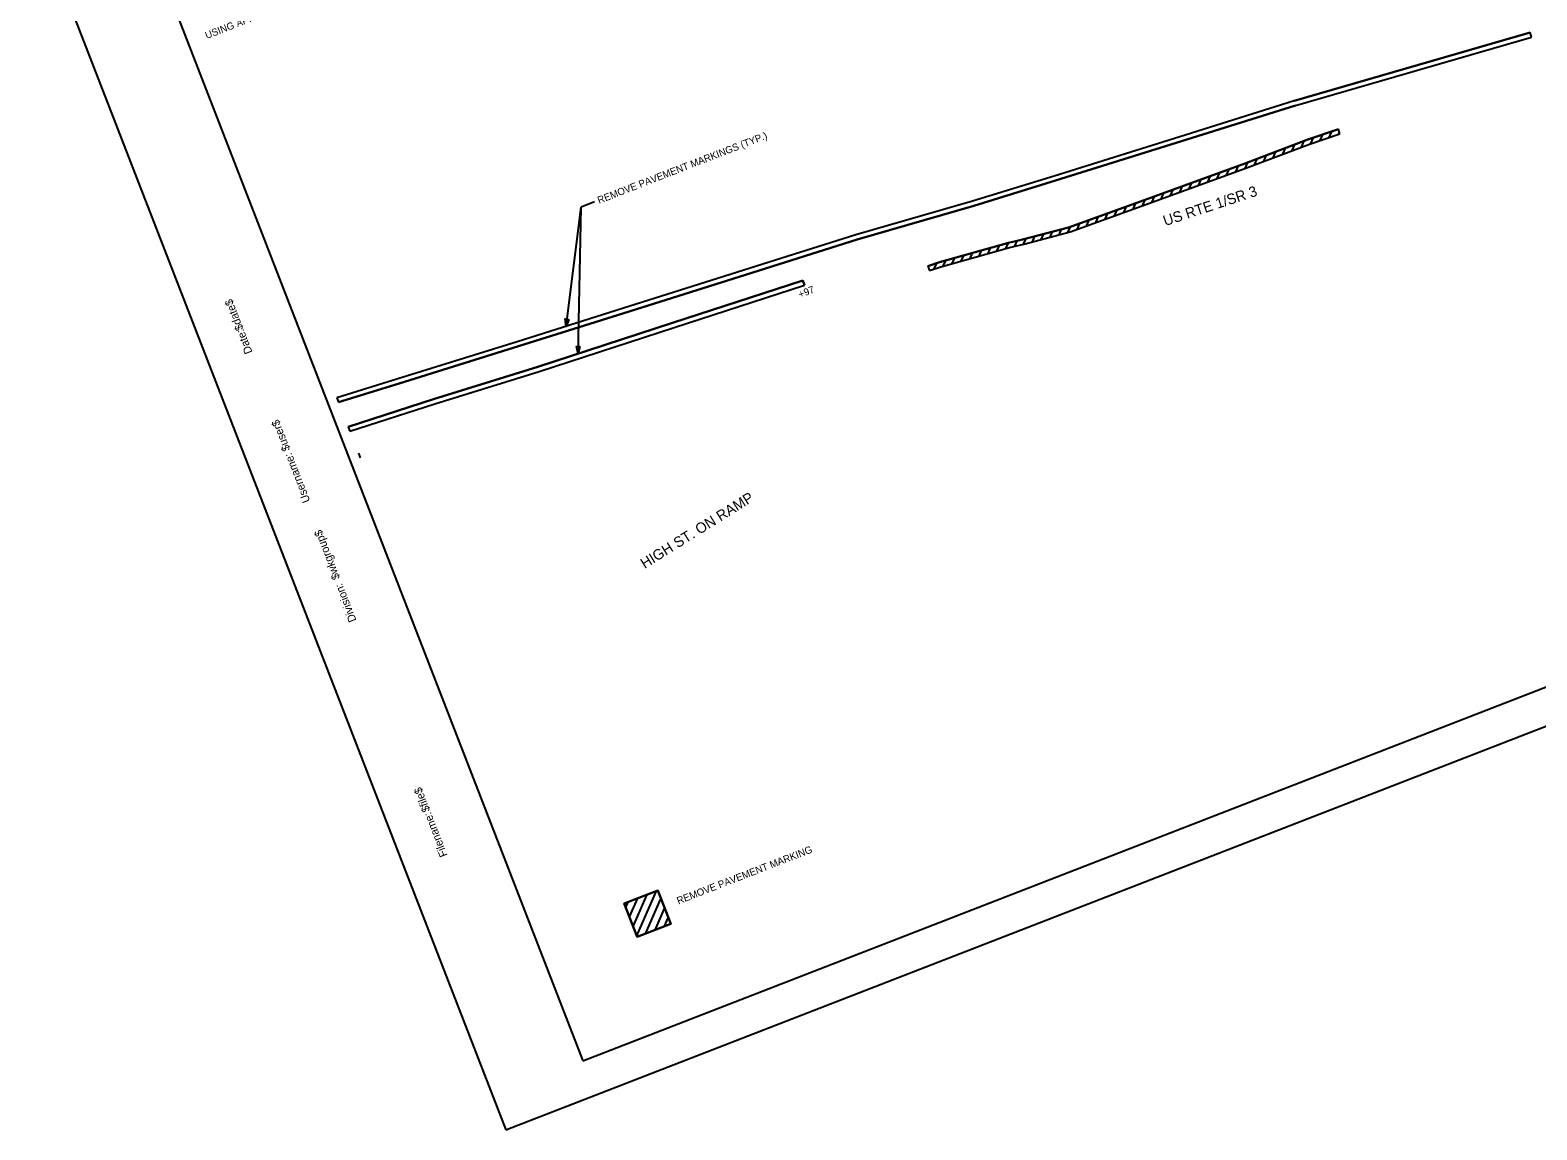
# Model space of a CAD drawing. Extents: x 1669098 to 1670090, y 339554 to 340375.
# Drawn here: x 1669098 to 1669728, y 339554 to 340014 of the extents above; entities that cross this region are included whole.
import ezdxf

# ---------------------------------------------------------------- set-up
doc = ezdxf.new("R2010")
doc.units = 0
for name, color, linetype in [('ANNOTATION', 7, 'Continuous'), ('BORDER', 7, 'Continuous'), ('PATTERNING', 7, 'Continuous'), ('PLOT BOUNDARY', 7, 'Continuous'), ('SHADING', 7, 'Continuous')]:
    doc.layers.add(name, color=color, linetype=linetype)

msp = doc.modelspace()

# ---------------------------------------------------------------- linework, layer by layer
at = {"layer": 'ANNOTATION'}
for p in [(1669334.25, 339942.45), (1669334.25, 339942.45), (1669334.25, 339942.45), (1669322.42, 339890.41), (1669327.39, 339878.97)]:
    msp.add_line(p, (1669328.66, 339940.28), dxfattribs=at)
for points in [[(1669323.54, 339893.3), (1669322.42, 339890.41), (1669322.05, 339893.48)], [(1669328.2, 339881.95), (1669327.39, 339878.97), (1669326.7, 339881.98)]]:
    msp.add_lwpolyline(points, close=True, dxfattribs=at)
at = {"layer": 'BORDER'}
for p, q in [((1669139.46, 340072.86), (1669329.32, 339583.39)), ((1669329.32, 339583.39), (1670075.18, 339872.71))]:
    msp.add_line(p, q, dxfattribs=at)
at = {"layer": 'PATTERNING'}
for p, q in [((1669626.94, 339984.72), (1669725.55, 340013.18)), ((1669725.55, 340013.18), (1669626.94, 339984.72)), ((1669627.49, 339982.8), (1669726.11, 340011.26)), ((1669627.49, 339982.8), (1669726.11, 340011.26)), ((1669726.11, 340011.26), (1669725.55, 340013.18)), ((1669726.11, 340011.26), (1669725.55, 340013.18)), ((1669629.98, 339965.36), (1669631.11, 339967.93)), ((1669632.67, 339968.51), (1669645.39, 339972.8)), ((1669633.3, 339966.62), (1669646.03, 339970.9)), ((1669633.9, 339966.82), (1669634.99, 339969.3)), ((1669637.75, 339968.12), (1669638.84, 339970.59)), ((1669641.6, 339969.41), (1669642.69, 339971.89)), ((1669646.03, 339970.9), (1669645.39, 339972.8)), ((1669645.45, 339970.71), (1669645.82, 339971.54)), ((1669610.3, 339957.93), (1669611.44, 339960.5)), ((1669614.24, 339959.42), (1669615.37, 339961.98)), ((1669618.17, 339960.9), (1669619.3, 339963.47)), ((1669622.11, 339962.39), (1669623.24, 339964.95)), ((1669626.04, 339963.88), (1669627.17, 339966.44)), ((1669594.65, 339952.17), (1669595.77, 339954.71)), ((1669598.56, 339953.6), (1669599.68, 339956.13)), ((1669602.46, 339955.02), (1669603.58, 339957.55)), ((1669606.37, 339956.44), (1669607.5, 339959.01)), ((1669579.03, 339946.48), (1669580.14, 339949.02)), ((1669582.93, 339947.91), (1669584.05, 339950.44)), ((1669586.84, 339949.33), (1669587.96, 339951.86)), ((1669590.74, 339950.75), (1669591.86, 339953.29)), ((1669559.5, 339939.38), (1669560.61, 339941.91)), ((1669563.4, 339940.79), (1669564.52, 339943.33)), ((1669567.31, 339942.22), (1669568.43, 339944.75)), ((1669571.21, 339943.64), (1669572.33, 339946.17)), ((1669575.12, 339945.06), (1669576.24, 339947.6)), ((1669543.9, 339933.76), (1669545.02, 339936.29)), ((1669547.8, 339935.16), (1669548.92, 339937.69)), ((1669551.7, 339936.57), (1669552.82, 339939.1)), ((1669555.6, 339937.97), (1669556.72, 339940.5)), ((1669521.13, 339926.73), (1669522.17, 339929.07)), ((1669524.84, 339927.71), (1669525.87, 339930.04)), ((1669528.55, 339928.68), (1669529.58, 339931.01)), ((1669532.26, 339929.65), (1669533.32, 339932.07)), ((1669536.11, 339930.95), (1669537.22, 339933.48)), ((1669540.01, 339932.35), (1669541.12, 339934.88)), ((1669498.86, 339920.84), (1669499.91, 339923.21)), ((1669502.6, 339921.88), (1669503.65, 339924.25)), ((1669506.34, 339922.93), (1669507.39, 339925.3)), ((1669510.04, 339923.89), (1669511.06, 339926.2)), ((1669513.72, 339924.79), (1669514.75, 339927.13)), ((1669517.43, 339925.76), (1669518.46, 339928.1)), ((1669476.35, 339914.4), (1669477.44, 339916.86)), ((1669480.16, 339915.6), (1669481.2, 339917.97)), ((1669483.9, 339916.65), (1669484.94, 339919.02)), ((1669487.64, 339917.7), (1669488.68, 339920.07)), ((1669491.38, 339918.74), (1669492.42, 339921.11)), ((1669495.12, 339919.79), (1669496.17, 339922.16)), ((1669473.7, 339915.62), (1669474.32, 339913.72)), ((1669421.43, 339909.52), (1669422.04, 339907.61)), ((1669422.04, 339907.61), (1669421.43, 339909.52)), ((1669227.23, 339858.7), (1669252.62, 339866.56)), ((1669226.51, 339860.57), (1669227.23, 339858.7)), ((1669226.51, 339860.57), (1669227.23, 339858.7)), ((1669231.23, 339848.39), (1669231.96, 339846.53)), ((1669231.23, 339848.39), (1669231.96, 339846.53)), ((1669235.52, 339837.35), (1669236.24, 339835.48)), ((1669350.44, 339639.56), (1669356.3, 339652.85)), ((1669351.98, 339635.6), (1669360.26, 339654.38)), ((1669347.37, 339647.47), (1669348.39, 339649.78)), ((1669348.91, 339643.51), (1669352.35, 339651.32)), ((1669355.65, 339636.51), (1669362.07, 339651.06)), ((1669359.61, 339638.04), (1669363.6, 339647.1)), ((1669363.57, 339639.58), (1669365.14, 339643.15))]:
    msp.add_line(p, q, dxfattribs=at)
for points in [[(1669626.94, 339984.72), (1669581.38, 339970.39), (1669526.5, 339953.23), (1669492.4, 339942.67), (1669443.62, 339928.65), (1669396.79, 339913.89), (1669343.28, 339897.01), (1669301.86, 339883.98), (1669252.02, 339868.47), (1669226.51, 339860.57)], [(1669626.91, 339984.71), (1669581.38, 339970.39), (1669526.5, 339953.23), (1669492.4, 339942.67), (1669443.62, 339928.65), (1669396.79, 339913.89), (1669343.28, 339897.01), (1669301.86, 339883.98), (1669252.02, 339868.47), (1669226.51, 339860.57)], [(1669627.51, 339982.8), (1669581.98, 339968.48), (1669527.09, 339951.32), (1669492.97, 339940.75), (1669444.19, 339926.74), (1669397.39, 339911.99), (1669343.88, 339895.1), (1669302.45, 339882.07), (1669252.62, 339866.56), (1669227.23, 339858.7)], [(1669252.62, 339866.56), (1669302.45, 339882.07), (1669343.88, 339895.1), (1669397.39, 339911.99), (1669444.19, 339926.74), (1669492.97, 339940.75), (1669527.09, 339951.32), (1669581.98, 339968.48), (1669627.49, 339982.8)], [(1669473.7, 339915.62), (1669478.5, 339917.22), (1669507.37, 339925.3), (1669513.28, 339926.74), (1669532.56, 339931.79), (1669560.71, 339941.94), (1669605.52, 339958.26), (1669632.63, 339968.5)], [(1669474.32, 339913.72), (1669479.08, 339915.3), (1669507.88, 339923.36), (1669513.77, 339924.81), (1669533.15, 339929.88), (1669561.39, 339940.06), (1669606.21, 339956.38), (1669633.34, 339966.63)], [(1669231.23, 339848.39), (1669266.9, 339859.9), (1669310.56, 339873.49), (1669366.96, 339891.87), (1669421.43, 339909.52)], [(1669421.43, 339909.52), (1669366.96, 339891.87), (1669310.56, 339873.49), (1669266.9, 339859.9), (1669231.23, 339848.39)], [(1669231.96, 339846.53), (1669267.5, 339857.99), (1669311.17, 339871.58), (1669367.57, 339889.96), (1669422.04, 339907.61)], [(1669231.96, 339846.53), (1669267.5, 339857.99), (1669311.17, 339871.58), (1669367.57, 339889.96), (1669422.04, 339907.61)]]:
    msp.add_lwpolyline(points, dxfattribs=at)
msp.add_lwpolyline([(1669346.73, 339649.14), (1669360.71, 339654.56), (1669366.14, 339640.58), (1669352.15, 339635.15)], close=True, dxfattribs=at)
at = {"layer": 'PLOT BOUNDARY'}
msp.add_lwpolyline([(1669297.13, 339554.5), (1670089.6, 339861.9), (1669890.69, 340374.67), (1669098.22, 340067.27)], close=True, dxfattribs=at)
at = {"layer": 'SHADING'}
for p, q in [((1669725.55, 340013.18), (1669626.94, 339984.72)), ((1669627.49, 339982.8), (1669726.11, 340011.26)), ((1669726.11, 340011.26), (1669725.55, 340013.18)), ((1669645.39, 339972.8), (1669632.63, 339968.5)), ((1669633.34, 339966.63), (1669646.03, 339970.9)), ((1669646.03, 339970.9), (1669645.39, 339972.8)), ((1669473.7, 339915.62), (1669474.32, 339913.72)), ((1669422.04, 339907.61), (1669421.43, 339909.52)), ((1669227.23, 339858.7), (1669252.62, 339866.56)), ((1669226.51, 339860.57), (1669227.23, 339858.7)), ((1669231.23, 339848.39), (1669231.96, 339846.53))]:
    msp.add_line(p, q, dxfattribs=at)
for points in [[(1669626.94, 339984.72), (1669581.38, 339970.39), (1669526.5, 339953.23), (1669492.4, 339942.67), (1669443.62, 339928.65), (1669396.79, 339913.89), (1669343.28, 339897.01), (1669301.86, 339883.98), (1669252.02, 339868.47), (1669226.51, 339860.57)], [(1669252.62, 339866.56), (1669302.45, 339882.07), (1669343.88, 339895.1), (1669397.39, 339911.99), (1669444.19, 339926.74), (1669492.97, 339940.75), (1669527.09, 339951.32), (1669581.98, 339968.48), (1669627.49, 339982.8)], [(1669632.63, 339968.5), (1669605.52, 339958.26), (1669560.71, 339941.94), (1669532.56, 339931.79), (1669513.28, 339926.74), (1669507.37, 339925.3), (1669478.5, 339917.22), (1669473.7, 339915.62)], [(1669474.32, 339913.72), (1669479.08, 339915.3), (1669507.88, 339923.36), (1669513.77, 339924.81), (1669533.15, 339929.88), (1669561.39, 339940.06), (1669606.21, 339956.38), (1669633.34, 339966.63)], [(1669421.43, 339909.52), (1669366.96, 339891.87), (1669310.56, 339873.49), (1669266.9, 339859.9), (1669231.23, 339848.39)], [(1669231.96, 339846.53), (1669267.5, 339857.99), (1669311.17, 339871.58), (1669367.57, 339889.96), (1669422.04, 339907.61)], [(1669352.15, 339635.15), (1669366.14, 339640.58), (1669360.71, 339654.56), (1669346.73, 339649.14), (1669352.15, 339635.15)]]:
    msp.add_lwpolyline(points, dxfattribs=at)

# ---------------------------------------------------------------- texts
at = {"layer": 'ANNOTATION'}
for s, height, rotation, p in [('USING APPROVED METHODS AND MATERIALS.', 3, 21.20129, (1669172.09, 340010.5)), ('REMOVE PAVEMENT MARKINGS (TYP.)', 3, 21.20129, (1669336.19, 339941.6)), ('REMOVE PAVEMENT MARKINGS (TYP.)', 3, 21.20129, (1669336.19, 339941.6)), ('REMOVE PAVEMENT MARKINGS (TYP.)', 3, 21.20129, (1669336.19, 339941.6)), ('US RTE 1/SR 3', 4.375, 18.2565, (1669572.95, 339932.29)), ('+97', 3, 21.20129, (1669420.24, 339902.2)), ('HIGH ST. ON RAMP', 4.375, 31.95234, (1669355.24, 339788.95)), ('REMOVE PAVEMENT MARKING', 3, 21.20129, (1669369.37, 339648.72))]:
    msp.add_text(s, height=height, rotation=rotation, dxfattribs=at).set_placement(p)
at = {"layer": 'BORDER'}
for s, p in [('$date$', (1669187.51, 339889.34)), ('Date:', (1669191.28, 339879.6)), ('$user$', (1669207.06, 339838.93)), ('Username:', (1669215.42, 339817.38)), ('$wkgroup$', (1669227.89, 339785.22)), ('Division:', (1669234.77, 339767.49)), ('$file$', (1669265.59, 339688.05)), ('Filename:', (1669272.87, 339669.28))]:
    msp.add_text(s, height=3.348, rotation=111.20129, dxfattribs=at).set_placement(p)

doc.saveas('drawing.dxf')
